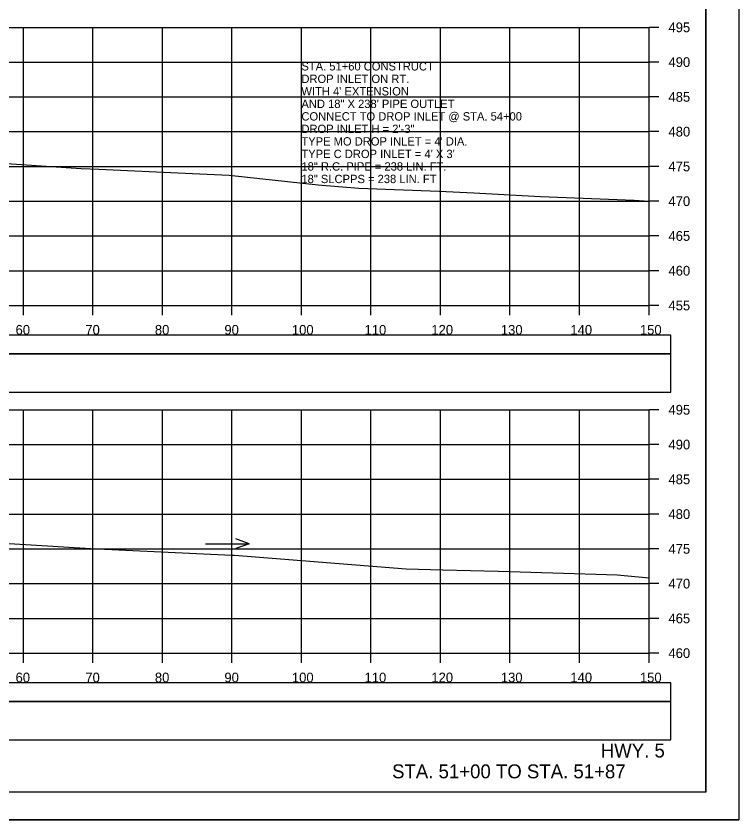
# Model space of a CAD drawing. Extents: x 1371057 to 1372761, y 380005 to 390517.
# Drawn here: x 1371619.8 to 1371723.8, y 383205.1 to 383320.8 of the extents above; entities that cross this region are included whole.
import ezdxf

# ---------------------------------------------------------------- set-up
doc = ezdxf.new("R2010")
doc.units = 0
for name, color, linetype in [('R_Axis', 7, 'Continuous'), ('R_Axis Annot', 7, 'Continuous'), ('R_Border', 7, 'Continuous'), ('R_Detour', 7, 'Continuous'), ('R_Dimension', 7, 'Continuous'), ('R_Draft', 7, 'Continuous'), ('R_Exist Surface', 7, 'Continuous'), ('R_Grid', 7, 'Continuous'), ('R_No Plot', 7, 'Continuous'), ('R_Water Annot', 7, 'Continuous')]:
    doc.layers.add(name, color=color, linetype=linetype)

msp = doc.modelspace()

# ---------------------------------------------------------------- linework, layer by layer
at = {"layer": 'R_Axis'}
for p, q in [((1371710.87, 383279.13), (1371710.87, 383319.13)), ((1371712.27, 383319.13), (1371710.87, 383319.13)), ((1371712.27, 383314.13), (1371710.87, 383314.13)), ((1371712.27, 383309.13), (1371710.87, 383309.13)), ((1371712.27, 383304.13), (1371710.87, 383304.13)), ((1371712.27, 383299.13), (1371710.87, 383299.13)), ((1371712.27, 383294.13), (1371710.87, 383294.13)), ((1371712.27, 383289.13), (1371710.87, 383289.13)), ((1371712.27, 383284.13), (1371710.87, 383284.13)), ((1371410.87, 383279.13), (1371710.87, 383279.13)), ((1371620.87, 383277.73), (1371620.87, 383279.13)), ((1371630.87, 383277.73), (1371630.87, 383279.13)), ((1371640.87, 383277.73), (1371640.87, 383279.13)), ((1371650.87, 383277.73), (1371650.87, 383279.13)), ((1371660.87, 383277.73), (1371660.87, 383279.13)), ((1371670.87, 383277.73), (1371670.87, 383279.13)), ((1371680.87, 383277.73), (1371680.87, 383279.13)), ((1371690.87, 383277.73), (1371690.87, 383279.13)), ((1371700.87, 383277.73), (1371700.87, 383279.13)), ((1371710.87, 383277.73), (1371710.87, 383279.13)), ((1371712.27, 383279.13), (1371710.87, 383279.13)), ((1371710.87, 383229.13), (1371710.87, 383264.13)), ((1371712.27, 383264.13), (1371710.87, 383264.13)), ((1371712.27, 383259.13), (1371710.87, 383259.13)), ((1371712.27, 383254.13), (1371710.87, 383254.13)), ((1371712.27, 383249.13), (1371710.87, 383249.13)), ((1371712.27, 383244.13), (1371710.87, 383244.13)), ((1371712.27, 383239.13), (1371710.87, 383239.13)), ((1371712.27, 383234.13), (1371710.87, 383234.13)), ((1371410.87, 383229.13), (1371710.87, 383229.13)), ((1371620.87, 383227.73), (1371620.87, 383229.13)), ((1371630.87, 383227.73), (1371630.87, 383229.13)), ((1371640.87, 383227.73), (1371640.87, 383229.13)), ((1371650.87, 383227.73), (1371650.87, 383229.13)), ((1371660.87, 383227.73), (1371660.87, 383229.13)), ((1371670.87, 383227.73), (1371670.87, 383229.13)), ((1371680.87, 383227.73), (1371680.87, 383229.13)), ((1371690.87, 383227.73), (1371690.87, 383229.13)), ((1371700.87, 383227.73), (1371700.87, 383229.13)), ((1371710.87, 383227.73), (1371710.87, 383229.13)), ((1371712.27, 383229.13), (1371710.87, 383229.13))]:
    msp.add_line(p, q, dxfattribs=at)
at = {"layer": 'R_Border'}
for q in [(1371719.05, 383414.59), (1371402.87, 383209.13)]:
    msp.add_line((1371719.05, 383209.13), q, dxfattribs=at)
at = {"layer": 'R_Detour'}
for points in [[(1371407.72, 383272.18), (1371714.03, 383272.18), (1371714.03, 383274.88), (1371407.72, 383274.88)], [(1371407.72, 383222.18), (1371714.03, 383222.18), (1371714.03, 383224.88), (1371407.72, 383224.88)]]:
    msp.add_lwpolyline(points, close=True, dxfattribs=at)
at = {"layer": 'R_Dimension'}
for points in [[(1371407.72, 383266.65), (1371714.03, 383266.65), (1371714.03, 383272.18), (1371407.72, 383272.18)], [(1371407.72, 383216.65), (1371714.03, 383216.65), (1371714.03, 383222.18), (1371407.72, 383222.18)]]:
    msp.add_lwpolyline(points, close=True, dxfattribs=at)
at = {"layer": 'R_Exist Surface'}
for points in [[(1371616.22, 383299.69), (1371629.19, 383298.82), (1371631.75, 383298.72), (1371644.15, 383298.15), (1371650.46, 383297.86), (1371663.27, 383296.48), (1371669.14, 383296), (1371680.7, 383295.56), (1371685.65, 383295.32), (1371695.28, 383294.79), (1371708.74, 383294.28), (1371710.87, 383294.11)], [(1371611.49, 383245.34), (1371622, 383244.72), (1371630.53, 383244.19), (1371650.87, 383243.23), (1371651.09, 383243.22), (1371651.23, 383243.21), (1371675.92, 383241.26), (1371681.19, 383241.12), (1371689.18, 383240.91), (1371697.04, 383240.69), (1371706.27, 383240.37), (1371710.87, 383239.96)]]:
    msp.add_lwpolyline(points, dxfattribs=at)
at = {"layer": 'R_Grid'}
for p, q in [((1371410.87, 383319.13), (1371710.87, 383319.13)), ((1371620.87, 383279.13), (1371620.87, 383319.13)), ((1371630.87, 383279.13), (1371630.87, 383319.13)), ((1371640.87, 383279.13), (1371640.87, 383319.13)), ((1371650.87, 383279.13), (1371650.87, 383319.13)), ((1371660.87, 383279.13), (1371660.87, 383319.13)), ((1371670.87, 383279.13), (1371670.87, 383319.13)), ((1371680.87, 383279.13), (1371680.87, 383319.13)), ((1371690.87, 383279.13), (1371690.87, 383319.13)), ((1371700.87, 383279.13), (1371700.87, 383319.13)), ((1371710.87, 383279.13), (1371710.87, 383319.13)), ((1371410.87, 383314.13), (1371710.87, 383314.13)), ((1371410.87, 383309.13), (1371710.87, 383309.13)), ((1371410.87, 383304.13), (1371710.87, 383304.13)), ((1371410.87, 383299.13), (1371710.87, 383299.13)), ((1371410.87, 383294.13), (1371710.87, 383294.13)), ((1371410.87, 383289.13), (1371710.87, 383289.13)), ((1371410.87, 383284.13), (1371710.87, 383284.13)), ((1371410.87, 383279.13), (1371710.87, 383279.13)), ((1371410.87, 383264.13), (1371710.87, 383264.13)), ((1371620.87, 383229.13), (1371620.87, 383264.13)), ((1371630.87, 383229.13), (1371630.87, 383264.13)), ((1371640.87, 383229.13), (1371640.87, 383264.13)), ((1371650.87, 383229.13), (1371650.87, 383264.13)), ((1371660.87, 383229.13), (1371660.87, 383264.13)), ((1371670.87, 383229.13), (1371670.87, 383264.13)), ((1371680.87, 383229.13), (1371680.87, 383264.13)), ((1371690.87, 383229.13), (1371690.87, 383264.13)), ((1371700.87, 383229.13), (1371700.87, 383264.13)), ((1371710.87, 383229.13), (1371710.87, 383264.13)), ((1371410.87, 383259.13), (1371710.87, 383259.13)), ((1371410.87, 383254.13), (1371710.87, 383254.13)), ((1371410.87, 383249.13), (1371710.87, 383249.13)), ((1371410.87, 383244.13), (1371710.87, 383244.13)), ((1371410.87, 383239.13), (1371710.87, 383239.13)), ((1371410.87, 383234.13), (1371710.87, 383234.13)), ((1371410.87, 383229.13), (1371710.87, 383229.13))]:
    msp.add_line(p, q, dxfattribs=at)
at = {"layer": 'R_No Plot'}
msp.add_line((1371390.47, 383205.15), (1371723.8, 383205.15), dxfattribs=at)
for points in [[(1371390.46, 383418.48), (1371723.8, 383418.48), (1371723.8, 383205.15), (1371390.46, 383205.15)], [(1371636.79, 383414.59), (1371656.41, 383414.59), (1371656.41, 383404.71), (1371672.52, 383404.71), (1371695.72, 383404.71), (1371695.84, 383376.55), (1371719.05, 383376.55), (1371719.05, 383209.13), (1371402.87, 383209.13), (1371402.87, 383414.59)]]:
    msp.add_lwpolyline(points, close=True, dxfattribs=at)
at = {"layer": 'R_Water Annot'}
for p, q in [((1371647.07, 383244.87), (1371653.35, 383244.87)), ((1371653.35, 383244.87), (1371651.43, 383245.57)), ((1371653.35, 383244.87), (1371651.43, 383244.17))]:
    msp.add_line(p, q, dxfattribs=at)

# ---------------------------------------------------------------- texts
at = {"layer": 'R_Axis Annot'}
for s, p in [('495', (1371713.67, 383318.43)), ('490', (1371713.67, 383313.43)), ('485', (1371713.67, 383308.43)), ('480', (1371713.67, 383303.43)), ('475', (1371713.67, 383298.43)), ('470', (1371713.67, 383293.43)), ('465', (1371713.67, 383288.43)), ('460', (1371713.67, 383283.43)), ('455', (1371713.67, 383278.43)), ('60', (1371619.75, 383274.93)), ('70', (1371629.79, 383274.93)), ('80', (1371639.79, 383274.93)), ('90', (1371649.79, 383274.93)), ('100', (1371659.5, 383274.93)), ('110', (1371669.95, 383274.93)), ('120', (1371679.56, 383274.93)), ('130', (1371689.56, 383274.93)), ('140', (1371699.56, 383274.93)), ('150', (1371709.56, 383274.93)), ('495', (1371713.67, 383263.43)), ('490', (1371713.67, 383258.43)), ('485', (1371713.67, 383253.43)), ('480', (1371713.67, 383248.43)), ('475', (1371713.67, 383243.43)), ('470', (1371713.67, 383238.43)), ('465', (1371713.67, 383233.43)), ('460', (1371713.67, 383228.43)), ('60', (1371619.75, 383224.93)), ('70', (1371629.79, 383224.93)), ('80', (1371639.79, 383224.93)), ('90', (1371649.79, 383224.93)), ('100', (1371659.5, 383224.93)), ('110', (1371669.95, 383224.93)), ('120', (1371679.56, 383224.93)), ('130', (1371689.56, 383224.93)), ('140', (1371699.56, 383224.93)), ('150', (1371709.56, 383224.93))]:
    msp.add_text(s, height=1.4, dxfattribs=at).set_placement(p)
at = {"layer": 'R_Draft'}
for s, p in [('HWY. 5', (1371703.93, 383214.12)), ('STA. 51+00 TO STA. 51+87', (1371673.91, 383211.13))]:
    msp.add_text(s, height=2, dxfattribs=at).set_placement(p)
at = {"layer": 'R_Water Annot'}
for s, p in [('STA. 51+60 CONSTRUCT', (1371660.87, 383312.93)), ('DROP INLET ON RT.', (1371660.87, 383311.13)), ("WITH 4' EXTENSION", (1371660.87, 383309.33)), ('AND 18" X 238\' PIPE OUTLET', (1371660.87, 383307.53)), ('CONNECT TO DROP INLET @ STA. 54+00', (1371660.87, 383305.73)), ('DROP INLET H = 2\'-3"', (1371660.87, 383303.93)), ("TYPE MO DROP INLET = 4' DIA.", (1371660.87, 383302.13)), ("TYPE C DROP INLET = 4' X 3'", (1371660.87, 383300.33)), ('18" R.C. PIPE = 238 LIN. FT.', (1371660.87, 383298.53)), ('18" SLCPPS = 238 LIN. FT', (1371660.87, 383296.73))]:
    msp.add_text(s, height=1.2, dxfattribs=at).set_placement(p)

doc.saveas('drawing.dxf')
